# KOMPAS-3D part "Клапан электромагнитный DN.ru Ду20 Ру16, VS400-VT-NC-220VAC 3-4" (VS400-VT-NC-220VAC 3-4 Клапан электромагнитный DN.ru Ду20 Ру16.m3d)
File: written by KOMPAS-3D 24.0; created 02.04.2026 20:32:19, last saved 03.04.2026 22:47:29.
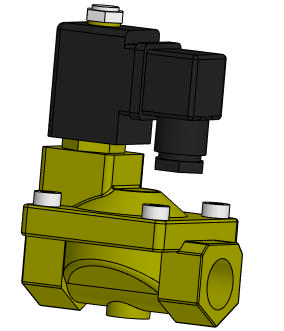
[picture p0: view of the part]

Document properties: Автор: artio; Полное имя файла: C:\Users\artio\OneDrive\Рабочий стол\Клапан электромагнитный DN.ru\VS400-VT-NC\VS400-VT-NC-220VAC 3-4 Клапан электромагнитный DN.ru Ду20 Ру16.m3d

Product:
- Body: Тело 1  | qty 1
    Масса: 1.210539
- Part/product: Клапан электромагнитный DN.ru Ду20 Ру16  | designation VS400-VT-NC-220VAC 3-4
    Масса: 0.954
    Раздел спецификации: Прочие изделия
    Примечание: D130-04699
    additional columns: ef56311e-7521-43dc-8291-0e6108b3d81d; VS400-ET-NC-220VAC 3-4; artio; c; Шероховатость не задана; Да

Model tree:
1. Операция без истории:1

Expressions: VS400-VT-NC-220VAC 3-4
